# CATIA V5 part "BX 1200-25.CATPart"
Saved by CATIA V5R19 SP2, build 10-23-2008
Part number: BX 1200-25
Bounding box of the stored display mesh (mm): x -59.975 to 59.975, y -59.975 to 59.975, z 0 to 155
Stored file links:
  C:\Users\Bora\Desktop\3D Katı model\BX serisi\BX 1200\BX 1200-25.CATPart
  C:\Program Files\Dassault Systemes\B19\intel_a\reffiles\standard\MetricThickPitch.txt
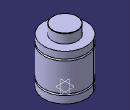
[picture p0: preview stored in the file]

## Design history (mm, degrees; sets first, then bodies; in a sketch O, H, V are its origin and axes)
Body1 (main body)
  Sketch1 on yz-plane, origin (0, 0, 0), H (0, 1, 0), V (0, 0, 1)
    point P2 (60, 20)
    line L1 (60, 20) -> (60, 0)
    point P3 (60, 25)
    point P4 (60, 105)
    line L2 (60, 105) -> (60, 25)
    point P6 (35, 154)
    arc A1 centre (34, 154) radius 1 from (35, 154) to (34, 155) ccw
    point P8 (35, 154)
    line L3 (35, 154) -> (35, 129)
    point P9 (60, 110)
    line L4 (60, 129) -> (60, 110)
    point P11 (60, 20)
    point P12 (60, 25)
    arc A2 centre (60, 22.5) radius 2.5 from (60, 25) to (60, 20) ccw
    point P13 (60, 105)
    point P14 (60, 110)
    arc A3 centre (60, 107.5) radius 2.5 from (60, 110) to (60, 105) ccw
    line L5 (34, 155) -> (0, 155)
    point P15 (0, 155)
    line L6 (35, 129) -> (60, 129)
    line L7 (60, 0) -> (0, 0)
    coincidence: P15 V, P2 P11, P3 P12, P4 P13, P6 P8, P9 P14
    horizontal: L5 H, L6 H, L7 H
  Shaft1: profile Sketch1, axis Sketch1.V, angle 360
  Sketch2 on face of Shaft1 from Sketch1.L7, origin (0, 0, 0), H (1, 0, 0), V (0, -1, 0)
    point P1 (32.5, 0)
    distance P1 V = 32.5
  Hole1: placed by Sketch2, at (32.5, 0, 0) direction (0, 0, 1), diameter 8.376, depth 10, threaded "M10", thread diameter 10, thread depth 10, pitch 1.5
  CircPattern1: of Hole1, instances 4, angular step 90, axis from xy-plane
